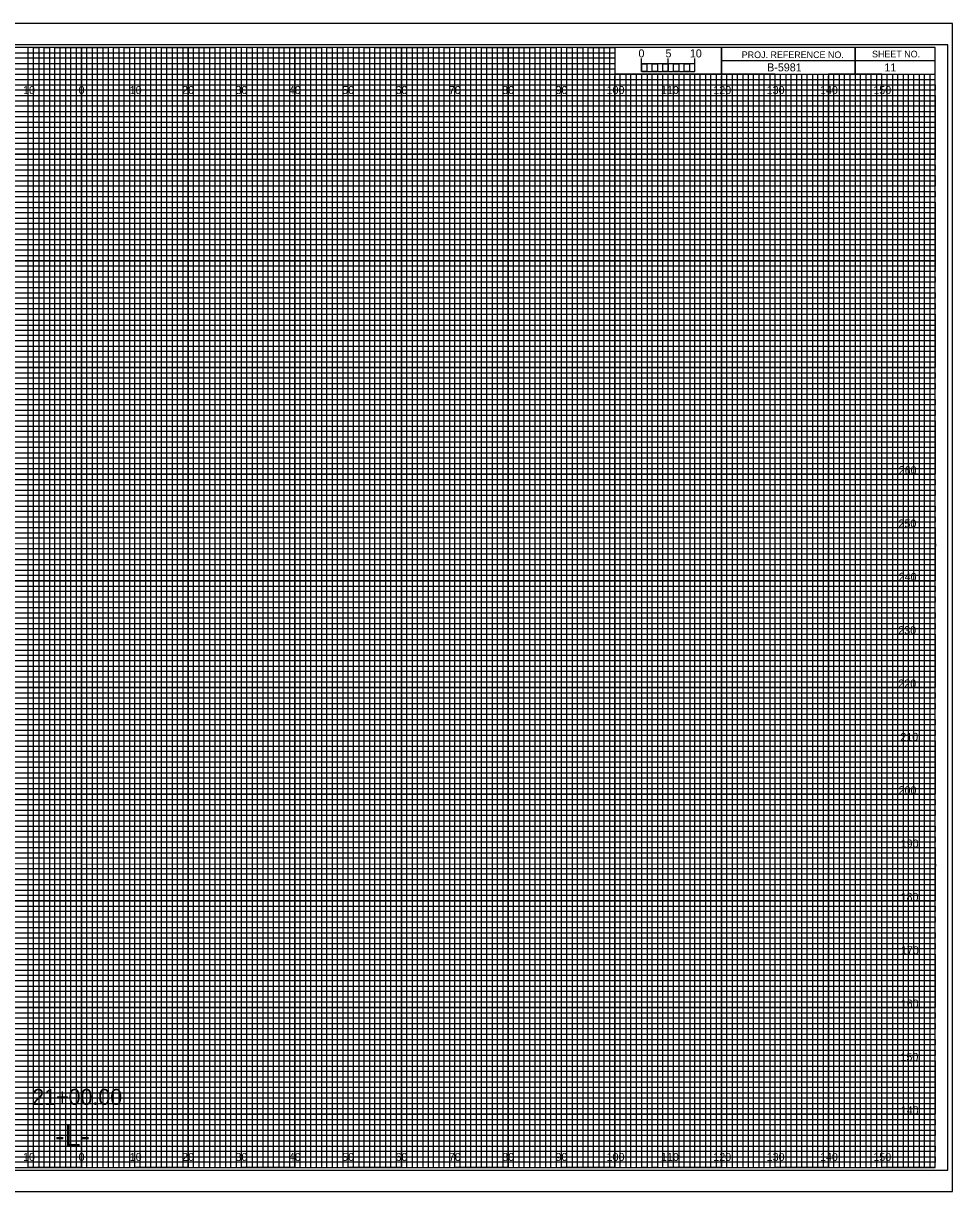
# Model space of a CAD drawing. Extents: x -13 to 323, y -5 to 1754.
# Drawn here: x 149.1 to 323.3, y 1535.5 to 1754.5 of the extents above; entities that cross this region are included whole.
import ezdxf

# ---------------------------------------------------------------- set-up
doc = ezdxf.new("R2010")
doc.units = 0
for name, color, linetype in [('Exist Cross Section Cell', 7, 'Continuous'), ('Exist XS Center Line Elevation Label', 7, 'Continuous'), ('Exist XS Ground Line', 7, 'Continuous'), ('Prop CMT Concrete Structures', 7, 'Continuous'), ('Prop CMT Guardrail Graphics', 7, 'Continuous'), ('Prop CMT Pvmt Course 1', 7, 'Continuous'), ('Prop CMT Pvmt Course 2', 7, 'Continuous'), ('Prop CMT Pvmt Course 3', 7, 'Continuous'), ('Prop CMT Pvmt Surface', 7, 'Continuous'), ('Prop CMT Shld Paved Course 1', 7, 'Continuous'), ('Prop CMT Shld Paved Course 2', 7, 'Continuous'), ('Prop CMT Shld Paved Course 3', 7, 'Continuous'), ('Prop CMT Subgrade Earthwork', 7, 'Continuous'), ('Prop XS Ditch Standard Text', 7, 'Continuous'), ('Prop XS SE Text', 7, 'Continuous'), ('Prop XS Side Slope Text', 7, 'Continuous'), ('Scratch_Level_0', 7, 'Continuous')]:
    doc.layers.add(name, color=color, linetype=linetype)

msp = doc.modelspace()

# ---------------------------------------------------------------- linework, layer by layer
at = {"layer": 'Exist XS Center Line Elevation Label'}
for points in [[(145, 1540), (155, 1540), (155, 1750), (165, 1750), (165, 1540), (175, 1540), (175, 1750), (185, 1750), (185, 1540), (195, 1540), (195, 1750), (205, 1750), (205, 1540), (215, 1540), (215, 1750), (225, 1750), (225, 1540), (235, 1540), (235, 1750), (245, 1750), (245, 1540), (255, 1540), (255, 1750), (259.93, 1750), (260, 1750), (260, 1745), (264.99, 1745), (264.99, 1540), (275, 1540), (275, 1745), (285, 1745), (285, 1540), (295, 1540), (295, 1745), (305, 1745), (305, 1540), (315, 1540), (315, 1745)], [(0, 1745), (275, 1745)], [(0, 1725), (320, 1725), (320, 1735), (0, 1735)], [(0, 1705), (320, 1705), (320, 1715), (0, 1715)], [(0, 1685), (320, 1685), (320, 1695), (0, 1695)], [(0, 1665), (320, 1665), (320, 1675), (0, 1675)], [(0, 1645), (320, 1645), (320, 1655), (0, 1655)], [(0, 1625), (320, 1625), (320, 1635), (0, 1635)], [(0, 1605), (320, 1605), (320, 1615), (0, 1615)], [(0, 1585), (320, 1585), (320, 1595), (0, 1595)], [(0, 1565), (320, 1565), (320, 1575), (0, 1575)], [(0, 1545), (320, 1545), (320, 1555), (0, 1555)]]:
    msp.add_lwpolyline(points, dxfattribs=at)
at = {"layer": 'Exist XS Ground Line'}
for p, q in [((150, 1750), (140, 1750)), ((150, 1540), (150, 1750)), ((170, 1750), (160, 1750)), ((160, 1750), (160, 1540)), ((170, 1540), (170, 1750)), ((190, 1750), (180, 1750)), ((180, 1750), (180, 1540)), ((190, 1540), (190, 1750)), ((210, 1750), (200, 1750)), ((200, 1750), (200, 1540)), ((210, 1540), (210, 1750)), ((230, 1750), (220, 1750)), ((220, 1750), (220, 1540)), ((230, 1540), (230, 1750)), ((250, 1750), (240, 1750)), ((240, 1750), (240, 1540)), ((250, 1540), (250, 1750)), ((260, 1750), (260, 1540)), ((270, 1540), (270, 1745)), ((290, 1745), (280, 1745)), ((280, 1745), (280, 1540)), ((290, 1540), (290, 1745)), ((310, 1745), (300, 1745)), ((300, 1745), (300, 1540)), ((310, 1540), (310, 1745)), ((160, 1540), (150, 1540)), ((180, 1540), (170, 1540)), ((200, 1540), (190, 1540)), ((220, 1540), (210, 1540)), ((240, 1540), (230, 1540)), ((260, 1540), (250, 1540)), ((280, 1540), (270, 1540)), ((300, 1540), (290, 1540)), ((320, 1540), (310, 1540)), ((320, 1540), (320, 1540))]:
    msp.add_line(p, q, dxfattribs=at)
for points in [[(0, 1740), (320, 1740), (320, 1730), (0, 1730)], [(0, 1720), (320, 1720), (320, 1710), (0, 1710)], [(0, 1700), (320, 1700), (320, 1690), (0, 1690)], [(0, 1680), (320, 1680), (320, 1670), (0, 1670)], [(0, 1660), (320, 1660), (320, 1650), (0, 1650)], [(0, 1640), (320, 1640), (320, 1630), (0, 1630)], [(0, 1620), (320, 1620), (320, 1610), (0, 1610)], [(0, 1600), (320, 1600), (320, 1590), (0, 1590)], [(0, 1580), (320, 1580), (320, 1570), (0, 1570)], [(0, 1560), (320, 1560), (320, 1550), (0, 1550)]]:
    msp.add_lwpolyline(points, dxfattribs=at)
at = {"layer": 'Prop CMT Pvmt Course 1'}
for p, q in [((323.3, 1754.5), (-13.4, 1754.5)), ((-13.4, 1535.5), (323.3, 1535.5))]:
    msp.add_line(p, q, dxfattribs=at)
at = {"layer": 'Prop CMT Pvmt Course 2'}
msp.add_lwpolyline([(-13.4, 1535.5), (323.3, 1535.5), (323.3, 1754.5), (-13.4, 1754.5)], close=True, dxfattribs=at)
at = {"layer": 'Prop CMT Pvmt Course 3'}
msp.add_lwpolyline([(-10.8, 1539.5), (322.4, 1539.5), (322.4, 1750.5), (-10.8, 1750.5)], close=True, dxfattribs=at)
at = {"layer": 'Prop CMT Shld Paved Course 1'}
for p, q in [((305, 1750), (305, 1745)), ((305, 1745), (305, 1750)), ((280, 1747.5), (280, 1745)), ((320, 1747.49), (280, 1747.49)), ((280, 1745), (320, 1745))]:
    msp.add_line(p, q, dxfattribs=at)
for points in [[(320, 1750), (0, 1750), (0, 1540), (320, 1540)], [(280, 1750), (260, 1750), (260, 1745.03), (280, 1745.03)], [(320, 1750), (280, 1750), (280, 1745), (320, 1745)]]:
    msp.add_lwpolyline(points, close=True, dxfattribs=at)
at = {"layer": 'Prop CMT Shld Paved Course 2'}
for p, q in [((267, 1745), (266.01, 1745)), ((266.01, 1745), (266.01, 1540)), ((267, 1540), (267, 1745)), ((269, 1745), (268, 1745)), ((268, 1745), (268, 1540)), ((269, 1540), (269, 1745)), ((266.01, 1540), (265, 1540)), ((268, 1540), (267, 1540))]:
    msp.add_line(p, q, dxfattribs=at)
for points in [[(150, 1540), (151, 1540), (151, 1750), (152, 1750), (152, 1540)], [(152, 1540), (153, 1540), (153, 1750), (154, 1750), (154, 1540)], [(155, 1540), (156, 1540), (156, 1750), (157, 1750), (157, 1540)], [(157, 1540), (158, 1540), (158, 1750), (159, 1750), (159, 1540)], [(160, 1540), (161, 1540), (161, 1750), (162, 1750), (162, 1540)], [(162, 1540), (163, 1540), (163, 1750), (164, 1750), (164, 1540)], [(165, 1540), (166, 1540), (166, 1750), (167, 1750), (167, 1540)], [(167, 1540), (168, 1540), (168, 1750), (169, 1750), (169, 1540)], [(170, 1540), (171, 1540), (171, 1750), (172, 1750), (172, 1540)], [(172, 1540), (173, 1540), (173, 1750), (174, 1750), (174, 1540)], [(175, 1540), (176, 1540), (176, 1750), (177, 1750), (177, 1540)], [(177, 1540), (178, 1540), (178, 1750), (179, 1750), (179, 1540)], [(180, 1540), (181, 1540), (181, 1750), (182, 1750), (182, 1540)], [(182, 1540), (183, 1540), (183, 1750), (184, 1750), (184, 1540)], [(185, 1540), (186, 1540), (186, 1750), (187, 1750), (187, 1540)], [(187, 1540), (188, 1540), (188, 1750), (189, 1750), (189, 1540)], [(190, 1540), (191, 1540), (191, 1750), (192, 1750), (192, 1540)], [(192, 1540), (193, 1540), (193, 1750), (194, 1750), (194, 1540)], [(195, 1540), (196, 1540), (196, 1750), (197, 1750), (197, 1540)], [(197, 1540), (198, 1540), (198, 1750), (199, 1750), (199, 1540)], [(200, 1540), (201, 1540), (201, 1750), (202, 1750), (202, 1540)], [(202, 1540), (203, 1540), (203, 1750), (204, 1750), (204, 1540)], [(205, 1540), (206, 1540), (206, 1750), (207, 1750), (207, 1540)], [(207, 1540), (208, 1540), (208, 1750), (209, 1750), (209, 1540)], [(210, 1540), (211, 1540), (211, 1750), (212, 1750), (212, 1540)], [(212, 1540), (213, 1540), (213, 1750), (214, 1750), (214, 1540)], [(215, 1540), (216, 1540), (216, 1750), (217, 1750), (217, 1540)], [(217, 1540), (218, 1540), (218, 1750), (219, 1750), (219, 1540)], [(220, 1540), (221, 1540), (221, 1750), (222, 1750), (222, 1540)], [(222, 1540), (223, 1540), (223, 1750), (224, 1750), (224, 1540)], [(225, 1540), (226, 1540), (226, 1750), (227, 1750), (227, 1540)], [(227, 1540), (228, 1540), (228, 1750), (229, 1750), (229, 1540)], [(230, 1540), (231, 1540), (231, 1750), (232, 1750), (232, 1540)], [(232, 1540), (233, 1540), (233, 1750), (234, 1750), (234, 1540)], [(235, 1540), (236, 1540), (236, 1750), (237, 1750), (237, 1540)], [(237, 1540), (238, 1540), (238, 1750), (239, 1750), (239, 1540)], [(240, 1540), (241, 1540), (241, 1750), (242, 1750), (242, 1540)], [(242, 1540), (243, 1540), (243, 1750), (244, 1750), (244, 1540)], [(245, 1540), (246, 1540), (246, 1750), (247, 1750), (247, 1540)], [(247, 1540), (248, 1540), (248, 1750), (249, 1750), (249, 1540)], [(250, 1540), (251, 1540), (251, 1750), (252, 1750), (252, 1540)], [(252, 1540), (253, 1540), (253, 1750), (254, 1750), (254, 1540)], [(255, 1540), (256, 1540), (256, 1750), (257, 1750), (257, 1540)], [(257, 1540), (258, 1540), (258, 1750), (259, 1750), (259, 1540)], [(260, 1540), (261, 1540), (261, 1745), (262.02, 1745), (262.02, 1540)], [(262, 1540), (263, 1540), (263, 1745), (263.99, 1745), (263.99, 1540)], [(270, 1540), (270.98, 1540), (270.98, 1745), (272, 1745), (272, 1540)], [(272, 1540), (273, 1540), (273, 1745), (274.05, 1745), (274.05, 1540)], [(275, 1540), (276, 1540), (276, 1745), (277, 1745), (277, 1540)], [(277, 1540), (278, 1540), (278, 1745), (279, 1745), (279, 1540)], [(280, 1540), (281, 1540), (281, 1745), (282, 1745), (282, 1540)], [(282, 1540), (283, 1540), (283, 1745), (284, 1745), (284, 1540)], [(285, 1540), (286, 1540), (286, 1745), (287, 1745), (287, 1540)], [(287, 1540), (288, 1540), (288, 1745), (289, 1745), (289, 1540)], [(290, 1540), (291, 1540), (291, 1745), (292, 1745), (292, 1540)], [(292, 1540), (293, 1540), (293, 1745), (294, 1745), (294, 1540)], [(295, 1540), (296, 1540), (296, 1745), (297, 1745), (297, 1540)], [(297, 1540), (298, 1540), (298, 1745), (299, 1745), (299, 1540)], [(300, 1540), (301, 1540), (301, 1745), (302, 1745), (302, 1540)], [(302, 1540), (303, 1540), (303, 1745), (304, 1745), (304, 1540)], [(305, 1540), (306, 1540), (306, 1745), (307, 1745), (307, 1540)], [(307, 1540), (308, 1540), (308, 1745), (309, 1745), (309, 1540)], [(310, 1540), (311, 1540), (311, 1745), (312, 1745), (312, 1540)], [(312, 1540), (313, 1540), (313, 1745), (314, 1745), (314, 1540)], [(315, 1540), (316, 1540), (316, 1745), (317, 1745), (317, 1540)], [(317, 1540), (318, 1540), (318, 1745), (319, 1745), (319, 1540)]]:
    msp.add_lwpolyline(points, dxfattribs=at)
at = {"layer": 'Prop CMT Shld Paved Course 3'}
for p, q in [((265, 1745.49), (265, 1747.9)), ((265, 1746.9), (265, 1747.9)), ((270, 1745.49), (270, 1747.9)), ((275, 1745.49), (275, 1747.9)), ((275, 1746.9), (275, 1747.9))]:
    msp.add_line(p, q, dxfattribs=at)
for points in [[(275, 1746.9), (265, 1746.9), (265, 1745.49), (275, 1745.49)], [(265, 1746.9), (266, 1746.9), (266, 1745.49), (265, 1745.49)], [(267, 1746.9), (268, 1746.9), (268, 1745.49), (267, 1745.49)], [(269, 1746.9), (270, 1746.9), (270, 1745.49), (269, 1745.49)], [(271, 1746.9), (272, 1746.9), (272, 1745.49), (271, 1745.49)], [(273, 1746.9), (274, 1746.9), (274, 1745.49), (273, 1745.49)]]:
    msp.add_lwpolyline(points, close=True, dxfattribs=at)
at = {"layer": 'Prop CMT Subgrade Earthwork'}
for p, q in [((150, 1540), (150, 1750)), ((160, 1540), (160, 1750)), ((170, 1540), (170, 1750)), ((180, 1540), (180, 1750)), ((190, 1540), (190, 1750)), ((200, 1540), (200, 1750)), ((210, 1540), (210, 1750)), ((220, 1540), (220, 1750)), ((230, 1540), (230, 1750)), ((240, 1540), (240, 1750)), ((250, 1540), (250, 1750)), ((260, 1540), (260, 1744.69)), ((270, 1540), (270, 1744.69)), ((280, 1540), (280, 1744.69)), ((290, 1540), (290, 1744.69)), ((300, 1540), (300, 1744.69)), ((310, 1540), (310, 1744.69)), ((0, 1740), (320, 1740)), ((0, 1730), (320, 1730)), ((0, 1720), (320, 1720)), ((0, 1710), (320, 1710)), ((0, 1700), (320, 1700)), ((0, 1690), (320, 1690)), ((0, 1680), (320, 1680)), ((0, 1670), (320, 1670)), ((0, 1660), (320, 1660)), ((0, 1650), (320, 1650)), ((0, 1640), (320, 1640)), ((0, 1630), (320, 1630)), ((0, 1620), (320, 1620)), ((0, 1610), (320, 1610)), ((0, 1600), (320, 1600)), ((0, 1590), (320, 1590)), ((0, 1580), (320, 1580)), ((0, 1570), (320, 1570)), ((0, 1560), (320, 1560)), ((0, 1550), (320, 1550))]:
    msp.add_line(p, q, dxfattribs=at)
at = {"layer": 'Scratch_Level_0'}
for p, q in [((0, 1749), (260, 1749)), ((260, 1747.98), (0, 1747.98)), ((260, 1749), (260, 1747.98)), ((0, 1747), (260, 1747)), ((260, 1745.89), (0, 1745.89)), ((260, 1747), (260, 1745.89)), ((0, 1744), (320, 1744))]:
    msp.add_line(p, q, dxfattribs=at)
for points in [[(0, 1743), (270, 1743), (320, 1743), (320, 1742), (0, 1742)], [(0, 1741), (320, 1741), (320, 1739), (0, 1739)], [(0, 1738), (320, 1738), (320, 1737), (0, 1736.98)], [(0, 1736), (320, 1736), (320, 1734), (0, 1734)], [(0, 1733), (320, 1733), (320, 1732), (0, 1732)], [(0, 1731), (320, 1731), (320, 1729), (0, 1729)], [(0, 1728), (320, 1728), (320, 1727), (0, 1727)], [(0, 1726), (320, 1726), (320, 1724), (0, 1724)], [(0, 1723), (320, 1723), (320, 1722), (0, 1722)], [(0, 1721), (320, 1721), (320, 1719), (0, 1719)], [(0, 1718), (320, 1718), (320, 1717), (0, 1717)], [(0, 1716), (320, 1716), (320, 1713.95), (320, 1713), (320, 1712), (0, 1712)], [(0, 1714), (320, 1714), (320, 1713), (0, 1713)], [(0, 1711), (320, 1711), (320, 1709), (0, 1709.03)], [(0, 1709.03), (320, 1709), (320, 1708), (0, 1708)], [(0, 1707), (320, 1707), (320, 1706), (0, 1706)], [(0, 1704), (320, 1704), (320, 1703), (0, 1703)], [(0, 1702), (320, 1702), (320, 1701), (0, 1701)], [(-0.07, 1698.89), (320, 1698.89), (320, 1697.88), (-0.07, 1697.88)], [(0, 1697), (320, 1697), (320, 1696), (0, 1696)], [(0, 1694), (320, 1694), (320, 1693), (0, 1693)], [(0, 1692), (320, 1692), (320, 1691), (0, 1691)], [(0, 1689), (320, 1689), (320, 1688), (0, 1688)], [(0, 1687), (320, 1687), (320, 1686), (0, 1686)], [(0, 1684), (320, 1684), (320, 1683), (0, 1683)], [(0, 1682), (320, 1682), (320, 1681), (0, 1681)], [(0, 1679), (320, 1679), (319.99, 1677.98), (0, 1678)], [(0, 1677), (320, 1677), (320, 1676), (0, 1676)], [(0, 1674), (320, 1674), (320, 1673), (0, 1673)], [(0, 1672), (320, 1672), (320, 1671), (0, 1671)], [(0, 1669), (320, 1669), (320, 1668), (0, 1668)], [(0, 1667), (320, 1667), (320, 1666), (0, 1666)], [(0, 1664), (320, 1664), (320, 1663), (0, 1663)], [(0, 1662), (320, 1662), (320, 1661), (0, 1661)], [(0, 1659), (320, 1659), (320, 1658), (0, 1658)], [(0, 1656.99), (320.07, 1656.91), (320, 1656), (0, 1656)], [(0, 1654), (320, 1654), (320, 1653), (0, 1653)], [(0, 1652), (320, 1652), (320, 1651), (0, 1651)], [(0, 1649), (320, 1649), (320, 1648), (0, 1648)], [(0, 1647), (320, 1647), (320, 1646), (0, 1646)], [(0, 1644), (320, 1644), (320, 1643), (0, 1643)], [(0, 1642), (320, 1642), (320, 1641), (0, 1641)], [(0, 1639), (320, 1639), (320, 1638), (0, 1638)], [(0, 1637), (320, 1637), (320, 1636), (0, 1636)], [(0, 1634), (320, 1634), (320, 1633), (0, 1633)], [(0, 1632), (320, 1632), (320, 1631), (0, 1631)], [(0, 1629), (320, 1629), (320, 1628), (0, 1628)], [(0, 1627), (320, 1627), (320, 1626), (0, 1626)], [(0, 1624), (320, 1624), (320, 1623), (0, 1623)], [(0, 1622), (320, 1622), (320, 1621), (0, 1621)], [(0, 1619), (320, 1619), (319.99, 1617.98), (0, 1618)], [(0, 1617), (320, 1617), (320, 1616), (0, 1616)], [(0, 1614), (320, 1614), (320, 1613), (0, 1613)], [(0, 1612), (320, 1612), (320, 1611), (0, 1611)], [(0, 1609), (320, 1609), (320, 1608), (0, 1608)], [(0, 1607), (320, 1607), (320, 1606), (0, 1606)], [(0, 1604), (320, 1604), (320, 1603), (0, 1603)], [(0, 1602), (320, 1602), (320, 1601), (0, 1601)], [(0, 1599), (320, 1599), (320, 1598), (0, 1598)], [(0, 1596.99), (320.07, 1596.91), (320, 1596), (0, 1596)], [(0, 1594), (320, 1594), (320, 1593), (0, 1593)], [(0, 1592), (320, 1592), (320, 1591), (0, 1591)], [(0, 1589), (320, 1589), (320, 1588), (0, 1588)], [(0, 1587), (320, 1587), (320, 1586), (0, 1586)], [(0, 1584), (320, 1584), (320, 1583), (0, 1583)], [(0, 1582), (320, 1582), (320, 1581), (0, 1581)], [(0, 1579), (320, 1579), (320, 1578), (0, 1578)], [(0, 1577), (320, 1577), (320, 1576), (0, 1576)], [(0, 1574), (320, 1574), (320, 1573), (0, 1573)], [(0, 1572), (320, 1572), (320, 1571), (0, 1571)], [(0, 1569), (320, 1569), (320, 1568), (0, 1568)], [(0, 1567), (320, 1567), (320, 1566), (0, 1566)], [(0, 1564), (320, 1564), (320, 1563), (0, 1563)], [(0, 1562), (320, 1562), (320, 1561), (0, 1561)], [(0, 1559), (320, 1559), (320, 1558), (0, 1558)], [(0, 1557), (320, 1557), (320, 1556), (0, 1556)], [(0, 1554), (320, 1554), (320, 1553), (0, 1553)], [(0, 1552), (320, 1552), (320, 1551), (0, 1551)], [(0, 1549), (320, 1549), (320, 1548), (0, 1548)], [(0, 1547), (320, 1547), (320, 1546), (0, 1546)], [(0, 1544), (320, 1544), (320, 1543), (0, 1543)], [(0, 1542), (320, 1542), (320, 1541), (0, 1541)]]:
    msp.add_lwpolyline(points, dxfattribs=at)

# ---------------------------------------------------------------- texts
at = {"layer": 'Exist Cross Section Cell'}
for s, p in [('260', (313.19, 1670)), ('250', (313.15, 1660)), ('240', (313.19, 1650)), ('230', (313.11, 1640)), ('220', (313.12, 1630)), ('210', (313.5, 1620)), ('200', (313.17, 1610)), ('190', (313.57, 1600)), ('180', (313.55, 1590)), ('170', (313.61, 1580)), ('160', (313.57, 1570)), ('150', (313.52, 1560)), ('140', (313.57, 1550))]:
    msp.add_text(s, height=1.5, dxfattribs=at).set_placement(p)
at = {"layer": 'Prop CMT Concrete Structures'}
msp.add_text('11', height=1.5, dxfattribs=at).set_placement((310.51, 1745.5))
at = {"layer": 'Prop CMT Guardrail Graphics'}
for s, p in [('5', (269.47, 1748.12)), ('10', (274.04, 1748.12))]:
    msp.add_text(s, height=1.5, dxfattribs=at).set_placement(p)
at = {"layer": 'Prop CMT Pvmt Surface'}
msp.add_text('21+00.00', height=3, dxfattribs=at).set_placement((150.77, 1551.76))
at = {"layer": 'Prop CMT Shld Paved Course 1'}
for s, p in [('PROJ. REFERENCE NO.', (283.77, 1747.99)), ('SHEET NO.', (308.19, 1748.12))]:
    msp.add_text(s, height=1.25, dxfattribs=at).set_placement(p)
at = {"layer": 'Prop CMT Shld Paved Course 3'}
msp.add_text('0', height=1.5, dxfattribs=at).set_placement((264.41, 1748.12))
at = {"layer": 'Prop XS Ditch Standard Text'}
for s, p in [('10', (149.04, 1741.25)), ('0', (159.45, 1741.25)), ('0', (159.45, 1741.25)), ('10', (169.04, 1741.25)), ('20', (178.86, 1741.25)), ('30', (188.86, 1741.25)), ('40', (198.86, 1741.25)), ('50', (208.86, 1741.25)), ('60', (218.86, 1741.25)), ('70', (228.86, 1741.25)), ('80', (238.86, 1741.25)), ('90', (248.86, 1741.25)), ('100', (258.44, 1741.25)), ('110', (268.62, 1741.25)), ('120', (278.44, 1741.25)), ('130', (288.44, 1741.25)), ('140', (298.44, 1741.25)), ('150', (308.44, 1741.25)), ('10', (149.04, 1541.25)), ('0', (159.45, 1541.25)), ('0', (159.45, 1541.25)), ('10', (169.04, 1541.25)), ('20', (178.86, 1541.25)), ('30', (188.86, 1541.25)), ('40', (198.86, 1541.25)), ('50', (208.86, 1541.25)), ('60', (218.86, 1541.25)), ('70', (228.86, 1541.25)), ('80', (238.86, 1541.25)), ('90', (248.86, 1541.25)), ('100', (258.44, 1541.25)), ('110', (268.62, 1541.25)), ('120', (278.44, 1541.25)), ('130', (288.44, 1541.25)), ('140', (298.44, 1541.25)), ('150', (308.44, 1541.25))]:
    msp.add_text(s, height=1.5, dxfattribs=at).set_placement(p)
at = {"layer": 'Prop XS SE Text'}
msp.add_text('-L-', height=4, dxfattribs=at).set_placement((155.06, 1544))
at = {"layer": 'Prop XS Side Slope Text'}
msp.add_text('B-5981', height=1.5, dxfattribs=at).set_placement((288.53, 1745.5))

doc.saveas('drawing.dxf')
